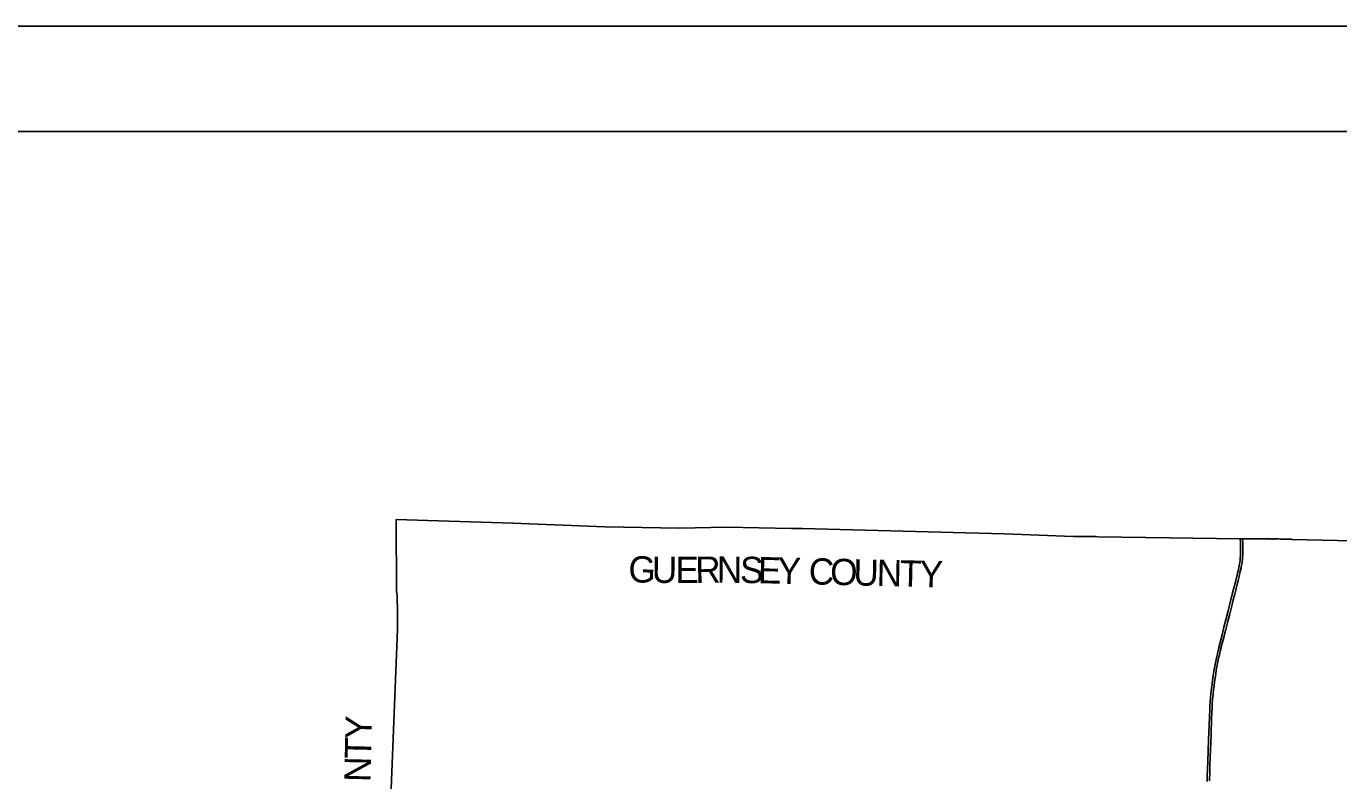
# Model space of a CAD drawing. Extents: x 2125567 to 2397567, y 653347 to 829347.
# Drawn here: x 2186868 to 2236793, y 800656 to 829347 of the extents above; entities that cross this region are included whole.
import ezdxf

# ---------------------------------------------------------------- set-up
doc = ezdxf.new("R2010")
doc.units = 0
for name, color, linetype in [('GM_X_County', 7, 'Continuous'), ('GM_X_County_Text', 7, 'Continuous'), ('SH_Border', 7, 'Continuous'), ('SH_Cut_Line', 7, 'Continuous'), ('UT_P_Electric', 7, 'Continuous')]:
    doc.layers.add(name, color=color, linetype=linetype)

msp = doc.modelspace()

# ---------------------------------------------------------------- linework, layer by layer
at = {"layer": 'GM_X_County'}
msp.add_lwpolyline([(2200752, 800346), (2200989, 806420), (2200992, 806538), (2200991, 806584), (2200991, 806637), (2200989, 806696), (2200988, 806732), (2200984, 806875), (2200986, 806939), (2200989, 807027), (2200988, 807107), (2200988, 807202), (2200988, 807267), (2200985, 807329), (2200980, 807397), (2200976, 807471), (2200975, 807541), (2200976, 807629), (2200976, 807730), (2200966, 807785), (2200946, 807855), (2200936, 810586), (2205381, 810448), (2208876, 810317), (2211703, 810263), (2213518, 810296), (2215979, 810248), (2216355, 810250), (2216390, 810249), (2222604, 810078), (2224073, 810043), (2226693, 809950), (2227550, 809938), (2227641, 809936), (2233044, 809853), (2233131, 809854), (2234115, 809853), (2234122, 809853), (2234142, 809852), (2234175, 809850), (2234208, 809849), (2234242, 809848), (2234269, 809847), (2234295, 809848), (2234328, 809849), (2234359, 809850), (2234386, 809850), (2234417, 809851), (2234474, 809852), (2234516, 809850), (2234560, 809848), (2234689, 809844), (2234803, 809842), (2234867, 809843), (2234901, 809842), (2234951, 809839), (2234985, 809837), (2235002, 809835), (2235020, 809833), (2237884, 809769)], dxfattribs=at)
at = {"layer": 'SH_Border'}
msp.add_lwpolyline([(2137567, 825347), (2393567, 825347), (2393567, 657347), (2137567, 657347)], close=True, dxfattribs=at)
at = {"layer": 'SH_Cut_Line'}
msp.add_lwpolyline([(2125567, 653347), (2397567, 653347), (2397567, 829347), (2125567, 829347)], close=True, dxfattribs=at)
at = {"layer": 'UT_P_Electric'}
for points in [[(2231787, 800627), (2231792, 800817), (2231814, 801384), (2231842, 802194), (2231854, 802485), (2231863, 802757), (2231875, 803108), (2231884, 803321), (2231894, 803511), (2231904, 803671), (2231915, 803815), (2231932, 803988), (2231951, 804164), (2231972, 804339), (2231991, 804482), (2232017, 804657), (2232054, 804881), (2232078, 805019), (2232102, 805142), (2232140, 805325), (2232176, 805488), (2232217, 805663), (2232239, 805751), (2232244, 805771), (2232291, 805959), (2232366, 806255), (2232426, 806493), (2232497, 806773), (2232586, 807123), (2232610, 807218), (2232638, 807329), (2232677, 807482), (2232757, 807804), (2232816, 808032), (2232916, 808423), (2232947, 808551), (2232974, 808673), (2232993, 808763), (2233009, 808856), (2233026, 808960), (2233037, 809048), (2233046, 809137), (2233053, 809235), (2233059, 809337), (2233061, 809435), (2233061, 809534), (2233059, 809626), (2233054, 809721), (2233045, 809850)], [(2231871, 800647), (2231884, 800994), (2231892, 801237), (2231916, 801853), (2231923, 802059), (2231936, 802426), (2231958, 803033), (2231965, 803236), (2231972, 803403), (2231983, 803586), (2231996, 803756), (2232013, 803943), (2232032, 804129), (2232049, 804266), (2232068, 804412), (2232112, 804704), (2232136, 804856), (2232159, 804982), (2232198, 805185), (2232224, 805314), (2232252, 805442), (2232285, 805586), (2232319, 805719), (2232325, 805744), (2232350, 805843), (2232418, 806107), (2232462, 806278), (2232496, 806412), (2232572, 806711), (2232644, 807001), (2232734, 807353), (2232782, 807541), (2232817, 807681), (2232836, 807753), (2232859, 807846), (2232874, 807903), (2232891, 807970), (2232915, 808073), (2232944, 808183), (2232965, 808263), (2233008, 808438), (2233049, 808613), (2233077, 808748), (2233084, 808787), (2233104, 808906), (2233113, 808968), (2233127, 809091), (2233132, 809140), (2233139, 809235), (2233144, 809314), (2233147, 809428), (2233148, 809494), (2233146, 809608), (2233145, 809664), (2233132, 809851)]]:
    msp.add_lwpolyline(points, dxfattribs=at)

# ---------------------------------------------------------------- texts
at = {"layer": 'GM_X_County_Text'}
for s, rotation, p in [('G', 358.8201, (2209766, 808203)), ('U', 359.1885, (2210657, 808184)), ('E', 0.1879, (2211561, 808172)), ('R', 0.9417, (2212323, 808174)), ('N', 359.4857, (2213130, 808188)), ('S', 359.0235, (2214012, 808180)), ('E', 358.7708, (2214689, 808168)), ('Y', 358.683, (2215436, 808152)), ('C', 358.6613, (2216624, 808125)), ('O', 358.6602, (2217438, 808106)), ('U', 358.6613, (2218322, 808085)), ('N', 358.6602, (2219206, 808064)), ('T', 358.6603, (2220090, 808044)), ('Y', 358.6603, (2220838, 808026)), ('Y', 88.6358, (2199998, 802228)), ('T', 88.6358, (2199980, 801482)), ('N', 88.6373, (2199959, 800599))]:
    msp.add_text(s, height=1000, rotation=rotation, dxfattribs=at).set_placement(p)

doc.saveas('drawing.dxf')
